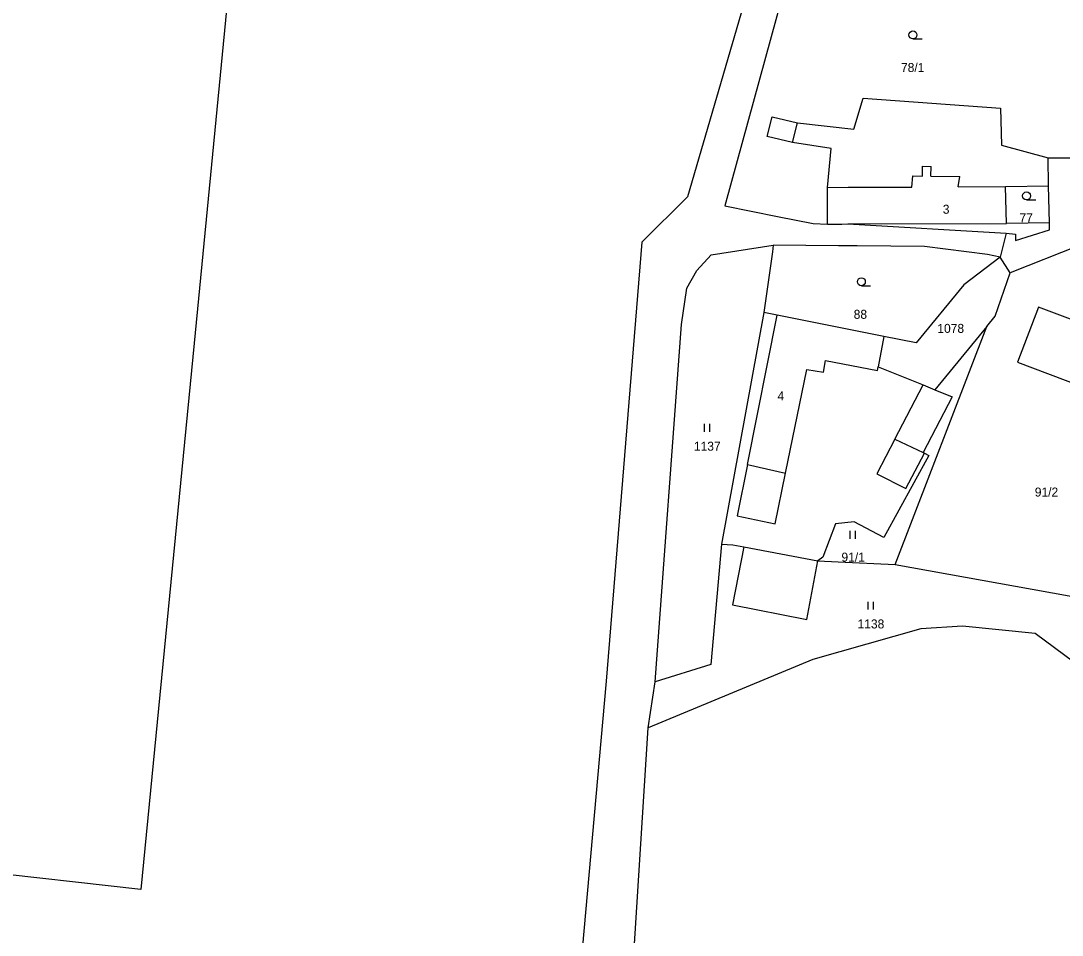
# Model space of a CAD drawing. Extents: x -746176 to -739709, y -1128407 to -1124482.
# Drawn here: x -742573.8 to -742377, y -1126240.2 to -1126067.4 of the extents above; entities that cross this region are included whole.
import ezdxf

# ---------------------------------------------------------------- set-up
doc = ezdxf.new("R2010")
doc.units = 0
for name, color, linetype in [('Vrstva 33', 7, 'Continuous'), ('Vrstva 42', 7, 'Continuous'), ('Vrstva 44', 7, 'Continuous'), ('Vrstva 47', 7, 'Continuous')]:
    doc.layers.add(name, color=color, linetype=linetype)

msp = doc.modelspace()

# ---------------------------------------------------------------- linework, layer by layer
at = {"layer": 'Vrstva 33'}
for p, q in [((-742379.56, -1126098.64), (-742379.6, -1126093.36)), ((-742379.39, -1126105.64), (-742379.56, -1126098.64)), ((-742387.54, -1126107.59), (-742388.7, -1126112.08)), ((-742386.77, -1126115.04), (-742388.7, -1126112.08)), ((-742389.6, -1126123.26), (-742386.77, -1126115.04)), ((-742433.38, -1126122.54), (-742441.38, -1126166.33)), ((-742391.19, -1126125.19), (-742389.6, -1126123.26)), ((-742408.55, -1126170.19), (-742391.19, -1126125.19)), ((-742391.19, -1126125.19), (-742401.05, -1126137.14)), ((-742408.55, -1126170.19), (-742366.28, -1126177.8)), ((-742455.22, -1126201.03), (-742453.88, -1126192.33))]:
    msp.add_line(p, q, dxfattribs=at)
for points in [[(-742530.79, -1126023.12), (-742541.03, -1126128.32), (-742551.09, -1126231.6), (-742645.51, -1126221.02)], [(-742433.87, -1126052.94), (-742447.8, -1126100.68), (-742456.41, -1126109.29), (-742463.16, -1126192.21), (-742472.54, -1126297.27), (-742476.24, -1126360.79), (-742482.39, -1126414.71)], [(-742427.68, -1126054.77), (-742440.74, -1126102.42), (-742430.76, -1126104.41), (-742424.03, -1126105.75), (-742421.29, -1126105.88)], [(-742421.29, -1126105.88), (-742421.35, -1126098.94), (-742420.61, -1126091.6), (-742427.91, -1126090.46), (-742432.7, -1126089.32), (-742431.8, -1126085.57), (-742427.02, -1126086.71), (-742416.37, -1126087.94), (-742414.61, -1126082.07), (-742388.6, -1126083.94), (-742388.43, -1126090.91), (-742379.6, -1126093.36)], [(-742379.6, -1126093.36), (-742370.19, -1126093.35), (-742362.62, -1126088.05), (-742361.35, -1126086.4)], [(-742379.39, -1126105.64), (-742387.46, -1126105.73), (-742387.67, -1126098.78), (-742379.56, -1126098.64)], [(-742421.29, -1126105.88), (-742418.62, -1126105.84), (-742417.46, -1126105.82), (-742387.54, -1126107.59)], [(-742387.54, -1126107.59), (-742385.77, -1126107.77), (-742385.76, -1126108.96), (-742379.36, -1126106.92), (-742379.39, -1126105.64)], [(-742453.88, -1126192.33), (-742448.94, -1126124.82), (-742447.92, -1126117.98), (-742446, -1126114.6), (-742443.31, -1126111.65), (-742431.56, -1126109.81)], [(-742431.56, -1126109.81), (-742431.74, -1126111.07), (-742433.38, -1126122.54)], [(-742388.7, -1126112.08), (-742391.06, -1126111.59), (-742402.96, -1126110.08), (-742415.74, -1126109.96), (-742419.27, -1126109.93), (-742431.56, -1126109.81)], [(-742351.14, -1126116.55), (-742365.05, -1126112.26), (-742373.77, -1126109.92), (-742386.77, -1126115.04)], [(-742388.7, -1126112.08), (-742395.57, -1126117.34), (-742404.55, -1126128.31), (-742410.69, -1126127.09)], [(-742410.69, -1126127.09), (-742430.85, -1126123.08), (-742433.38, -1126122.54)], [(-742360.61, -1126129.44), (-742370.56, -1126125.67), (-742369.93, -1126124), (-742372.74, -1126122.95), (-742373.37, -1126124.6), (-742381.46, -1126121.54), (-742385.41, -1126131.94), (-742364.54, -1126139.8), (-742360.61, -1126129.44)], [(-742410.69, -1126127.09), (-742411.76, -1126132.8), (-742403.21, -1126136.23), (-742401.05, -1126137.14)], [(-742401.05, -1126137.14), (-742397.77, -1126138.5), (-742403.21, -1126149.03), (-742402.98, -1126149.15), (-742402.18, -1126149.59), (-742410.69, -1126165.08), (-742416.29, -1126162.13), (-742419.8, -1126162.46), (-742422.21, -1126168.79), (-742423.12, -1126169.49)], [(-742441.38, -1126166.33), (-742443.37, -1126189.04), (-742453.88, -1126192.33)], [(-742441.38, -1126166.33), (-742439.21, -1126166.45), (-742437.12, -1126166.85), (-742439.28, -1126177.82), (-742425.2, -1126180.54), (-742423.12, -1126169.49)], [(-742423.12, -1126169.49), (-742419.32, -1126169.67), (-742408.55, -1126170.19)], [(-742371.13, -1126191.3), (-742382.1, -1126183.23), (-742395.78, -1126181.85), (-742403.65, -1126182.31), (-742424.12, -1126188.09), (-742455.22, -1126201.03)], [(-742521.95, -1126773.52), (-742504.56, -1126672.68), (-742497, -1126628.23), (-742488.98, -1126567.9), (-742478.35, -1126466.13), (-742467.6, -1126363.23), (-742463.32, -1126296.13), (-742459.73, -1126263.65), (-742452.82, -1126263.88), (-742450.23, -1126260.63), (-742452.38, -1126257.65), (-742458.75, -1126256.81), (-742455.22, -1126201.03)]]:
    msp.add_lwpolyline(points, dxfattribs=at)
at = {"layer": 'Vrstva 44'}
for p, q in [((-742405.18, -1126070.87), (-742403.43, -1126070.87)), ((-742383.7, -1126101.27), (-742381.95, -1126101.27)), ((-742414.92, -1126117.5), (-742413.17, -1126117.5)), ((-742444.57, -1126145.12), (-742444.57, -1126143.62)), ((-742443.57, -1126145.12), (-742443.57, -1126143.62)), ((-742417.04, -1126165.29), (-742417.04, -1126163.79)), ((-742416.04, -1126165.29), (-742416.04, -1126163.79)), ((-742413.64, -1126178.7), (-742413.64, -1126177.2)), ((-742412.64, -1126178.7), (-742412.64, -1126177.2))]:
    msp.add_line(p, q, dxfattribs=at)
for centre in [(-742405.18, -1126070.12), (-742383.7, -1126100.52), (-742414.92, -1126116.75)]:
    msp.add_circle(centre, 0.75, dxfattribs=at)
at = {"layer": 'Vrstva 47'}
for p, q in [((-742427.91, -1126090.46), (-742427.02, -1126086.71)), ((-742403.39, -1126096.78), (-742403.37, -1126094.93)), ((-742403.37, -1126094.93), (-742401.75, -1126094.95)), ((-742401.77, -1126096.8), (-742401.75, -1126094.95)), ((-742405.37, -1126098.85), (-742405.22, -1126096.76)), ((-742405.22, -1126096.76), (-742403.39, -1126096.78)), ((-742401.77, -1126096.8), (-742396.32, -1126096.85)), ((-742396.62, -1126098.81), (-742396.32, -1126096.85)), ((-742421.35, -1126098.94), (-742417.44, -1126098.9)), ((-742417.44, -1126098.9), (-742405.37, -1126098.85)), ((-742396.62, -1126098.81), (-742387.67, -1126098.78)), ((-742417.46, -1126105.82), (-742387.46, -1126105.73)), ((-742436.45, -1126151.3), (-742430.85, -1126123.08)), ((-742422.1, -1126133.81), (-742421.67, -1126131.64)), ((-742421.67, -1126131.64), (-742411.89, -1126133.49)), ((-742411.89, -1126133.49), (-742411.76, -1126132.8)), ((-742429.26, -1126152.92), (-742425.23, -1126133.31)), ((-742425.23, -1126133.31), (-742422.1, -1126133.81)), ((-742408.58, -1126146.46), (-742403.21, -1126136.23)), ((-742408.58, -1126146.46), (-742411.97, -1126153.04)), ((-742408.58, -1126146.46), (-742403.21, -1126149.03)), ((-742406.52, -1126155.83), (-742402.98, -1126149.15)), ((-742436.45, -1126151.3), (-742438.39, -1126161)), ((-742436.45, -1126151.3), (-742429.26, -1126152.92)), ((-742431.21, -1126162.5), (-742429.26, -1126152.92)), ((-742411.97, -1126153.04), (-742406.52, -1126155.83)), ((-742438.39, -1126161), (-742431.21, -1126162.5)), ((-742437.12, -1126166.85), (-742423.12, -1126169.49))]:
    msp.add_line(p, q, dxfattribs=at)

# ---------------------------------------------------------------- texts
at = {"layer": 'Vrstva 42'}
for s, p in [('78/1', (-742407.43, -1126077.12)), ('3', (-742399.53, -1126103.9)), ('77', (-742385.04, -1126105.53)), ('88', (-742416.37, -1126123.75)), ('1078', (-742400.56, -1126126.41)), ('4', (-742430.78, -1126139.17)), ('1137', (-742446.57, -1126148.67)), ('91/2', (-742382.14, -1126157.33)), ('91/1', (-742418.68, -1126169.63)), ('1138', (-742415.64, -1126182.25))]:
    msp.add_text(s, height=1.7, dxfattribs=at).set_placement(p)

doc.saveas('drawing.dxf')
